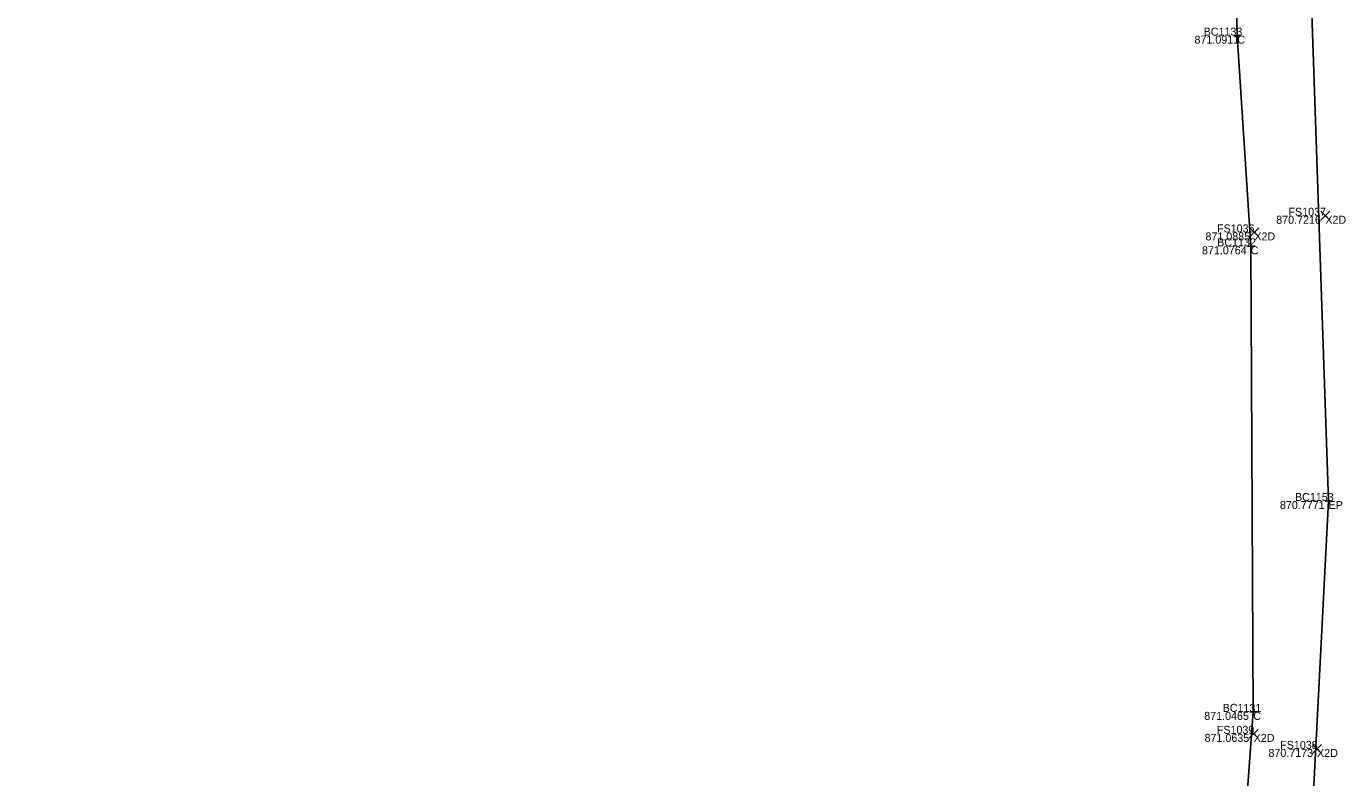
# Model space of a CAD drawing. Extents: x 1479425 to 1480294, y 379351 to 380102.
# Drawn here: x 1479564.08 to 1479573.97, y 379927.03 to 379932.66 of the extents above; entities that cross this region are included whole.
import ezdxf

# ---------------------------------------------------------------- set-up
doc = ezdxf.new("R2010")
doc.units = 0
for name, color, linetype in [('PV_X_Curb', 7, 'Continuous'), ('SV_X_Random_Point', 7, 'Continuous'), ('SV_X_Shot_Marker', 7, 'Continuous'), ('SV_X_Text_Comment', 7, 'Continuous'), ('SV_X_Text_Elevation', 7, 'Continuous'), ('SV_X_Text_Name', 7, 'Continuous')]:
    doc.layers.add(name, color=color, linetype=linetype)

msp = doc.modelspace()

# ---------------------------------------------------------------- linework, layer by layer
at = {"layer": 'PV_X_Curb'}
for points in [[(1479569.7374, 379946.0713), (1479571.6786, 379941.966), (1479572.2211, 379940.3862), (1479572.8837, 379937.5528), (1479573.4441, 379934.9926), (1479573.7165, 379932.7579), (1479573.8423, 379929.1036), (1479573.6746, 379925.8552), (1479573.045, 379921.8877), (1479571.771, 379917.2335), (1479569.497, 379912.1606), (1479567.166, 379908.6426), (1479563.944, 379905.002), (1479559.953, 379901.7586), (1479555.611, 379898.8117), (1479545.712, 379894.1043)], [(1479569.6747, 379945.147), (1479571.1449, 379941.9283), (1479571.2063, 379941.7143), (1479571.6328, 379940.3278), (1479572.0894, 379938.7326), (1479572.5276, 379936.8356), (1479573.0389, 379933.6479), (1479573.0983, 379933.4742), (1479573.1518, 379932.7783), (1479573.1584, 379932.5909), (1479573.2592, 379931.0122), (1479573.2781, 379927.5231), (1479573.155, 379925.8406), (1479572.586, 379922.1301), (1479571.403, 379917.5039), (1479569.157, 379912.5107), (1479566.948, 379909.0554), (1479563.851, 379905.5223), (1479559.694, 379902.1479), (1479555.354, 379899.3068), (1479545.42, 379894.5976)]]:
    msp.add_lwpolyline(points, dxfattribs=at)
at = {"layer": 'SV_X_Random_Point'}
for p, q in [((1479573.7847, 379931.2075), (1479573.8513, 379931.2743)), ((1479573.7847, 379931.2743), (1479573.8513, 379931.2075)), ((1479573.2527, 379931.0827), (1479573.3193, 379931.1495)), ((1479573.2527, 379931.1495), (1479573.3193, 379931.0827)), ((1479573.2477, 379927.3249), (1479573.3143, 379927.3917)), ((1479573.2477, 379927.3917), (1479573.3143, 379927.3249)), ((1479573.7227, 379927.212), (1479573.7893, 379927.2788)), ((1479573.7227, 379927.2788), (1479573.7893, 379927.212))]:
    msp.add_line(p, q, dxfattribs=at)
at = {"layer": 'SV_X_Shot_Marker'}
for p, q in [((1479573.1834, 379932.5918), (1479573.1334, 379932.59)), ((1479573.1575, 379932.6159), (1479573.1593, 379932.5659)), ((1479573.1584, 379932.5909), (1479573.1584, 379932.5909)), ((1479573.2841, 379931.0138), (1479573.2342, 379931.0106)), ((1479573.2576, 379931.0372), (1479573.2608, 379930.9873)), ((1479573.2592, 379931.0122), (1479573.2592, 379931.0122)), ((1479573.8414, 379929.1286), (1479573.8432, 379929.0786)), ((1479573.8673, 379929.1045), (1479573.8173, 379929.1028)), ((1479573.8423, 379929.1036), (1479573.8423, 379929.1036)), ((1479573.278, 379927.5481), (1479573.2782, 379927.4981)), ((1479573.3031, 379927.5233), (1479573.2531, 379927.523)), ((1479573.2781, 379927.5231), (1479573.2781, 379927.5231))]:
    msp.add_line(p, q, dxfattribs=at)

# ---------------------------------------------------------------- texts
at = {"layer": 'SV_X_Text_Comment'}
for s, p in [('C', (1479573.1584, 379932.5309)), ('X2D', (1479573.818, 379931.1809)), ('X2D', (1479573.286, 379931.0561)), ('C', (1479573.2592, 379930.9522)), ('EP', (1479573.8423, 379929.0436)), ('C', (1479573.2781, 379927.4631)), ('X2D', (1479573.281, 379927.2983)), ('X2D', (1479573.756, 379927.1854))]:
    msp.add_text(s, height=0.06, dxfattribs=at).set_placement(p)
at = {"layer": 'SV_X_Text_Elevation'}
for s, p in [('871.0911', (1479572.8376, 379932.5309)), ('870.7216', (1479573.45, 379931.1809)), ('871.0885', (1479572.9199, 379931.0561)), ('871.0764', (1479572.8936, 379930.9522)), ('870.7771', (1479573.478, 379929.0436)), ('871.0465', (1479572.9106, 379927.4631)), ('871.0635', (1479572.913, 379927.2983)), ('870.7173', (1479573.3918, 379927.1854))]:
    msp.add_text(s, height=0.06, dxfattribs=at).set_placement(p)
at = {"layer": 'SV_X_Text_Name'}
for s, p in [('BC1133', (1479572.9062, 379932.5909)), ('FS1037', (1479573.5421, 379931.2409)), ('FS1036', (1479573.0064, 379931.1161)), ('BC1132', (1479573.0075, 379931.0122)), ('BC1153', (1479573.591, 379929.1036)), ('BC1131', (1479573.0485, 379927.5231)), ('FS1039', (1479573.0047, 379927.3583)), ('FS1038', (1479573.4797, 379927.2454))]:
    msp.add_text(s, height=0.06, dxfattribs=at).set_placement(p)

doc.saveas('drawing.dxf')
